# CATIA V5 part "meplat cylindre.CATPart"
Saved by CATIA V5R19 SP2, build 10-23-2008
Part number: base cylindre
Bounding box of the stored display mesh (mm): x 0 to 100, y -25 to 25, z -26 to 0
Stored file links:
  C:\Users\Romain\Documents\IFMA\2A\cours\S3\Projet CFAO-IAO\IAO\Catia\Cylindre\meplat cylindre.CATPart
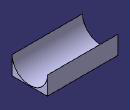
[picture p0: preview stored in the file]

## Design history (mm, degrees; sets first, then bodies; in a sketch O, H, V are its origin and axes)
Body1 (main body)
  Sketch1 on yz-plane, origin (0, 0, 0), H (0, 1, 0), V (0, 0, 1)
    line L1 (-25, 0) -> (-25, -26)
    point P1 (-25, 0)
    line L2 (-25, -26) -> (25, -26)
    line L3 (25, -26) -> (25, 0)
    point P4 (25, 0)
    arc A1 centre (0, 0) radius 25 from (-25, 0) to (25, 0) ccw
    length L1 = 26
    distance O L3 = 25
    coincidence: P1 H, P4 H
    vertical: L1 V, L3 V
    horizontal: L2 H
    tangency: A1 L1, A1 L3
  Pad1: profile Sketch1, direction (1, 0, 0), length 100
